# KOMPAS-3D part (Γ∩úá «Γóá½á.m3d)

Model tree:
1. Эскиз:1
2. Операция выдавливания:1
     Расстояние 1 = 15; Расстояние 2 = 30
3. Эскиз:2
4. Операция выдавливания:2
     Расстояние 1 = 4; Расстояние 2 = 30
5. Эскиз:3
6. Вырезать элемент выдавливания:1
     Расстояние 1 = 19
7. Эскиз:4
8. Вырезать элемент выдавливания:2
     Расстояние 1 = 2
9. Скругление:1
     Радиус = 0.5
10. Скругление:2
     Радиус = 0.5

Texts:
  Сплав АЛ8  ГОСТ 1583-93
